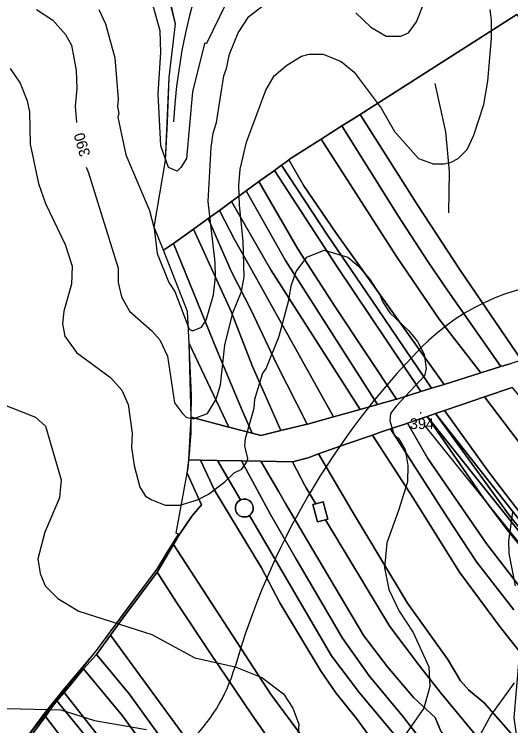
# Model space of a CAD drawing. Extents: x -510989 to -501240, y -1184665 to -1176098.
# Drawn here: x -505829.8 to -505553.2, y -1181865.9 to -1181469.7 of the extents above; entities that cross this region are included whole.
import ezdxf

# ---------------------------------------------------------------- set-up
doc = ezdxf.new("R2010")
doc.units = 0
for name, color, linetype in [('lesni_pozemek', 7, 'Continuous'), ('NAVRH_interakcni_prvky', 7, 'Continuous'), ('NAVRH_rozvodnice', 7, 'Continuous'), ('orna_puda', 7, 'Continuous'), ('ostatni_plocha_x_jina_plocha', 7, 'Continuous'), ('ostatni_plocha_x_ostatni_komunikace', 7, 'Continuous'), ('ostatni_plocha_x_silnice', 7, 'Continuous'), ('popis', 7, 'Continuous'), ('STAV_vyrazne_udolnice', 7, 'Continuous'), ('trasovani_toku', 7, 'Continuous'), ('trvaly_travni_porost', 7, 'Continuous'), ('vrstevnice_01', 7, 'Continuous'), ('vrstevnice_02', 7, 'Continuous'), ('vrstevnice_04', 7, 'Continuous'), ('vrstevnice_05', 7, 'Continuous')]:
    doc.layers.add(name, color=color, linetype=linetype)

msp = doc.modelspace()

# ---------------------------------------------------------------- linework, layer by layer
at = {"layer": 'lesni_pozemek'}
msp.add_lwpolyline([(-505549.95, -1181469.86), (-505637.13, -1181525.45), (-505642.17, -1181528.66), (-505647.29, -1181531.93), (-505658.89, -1181539.32), (-505676.4, -1181550.49), (-505676.84, -1181550.81), (-505678.71, -1181552.17), (-505680.89, -1181553.76), (-505684.89, -1181556.66), (-505693.47, -1181562.91), (-505700.54, -1181568.06), (-505708.78, -1181574.05), (-505715.54, -1181578.97), (-505721.81, -1181583.53), (-505729.98, -1181589.4), (-505740.99, -1181597.3), (-505744.98, -1181599.97), (-505746.66, -1181601.09), (-505751.84, -1181588.19), (-505745.47, -1181551.2), (-505744.49, -1181529.77), (-505743.54, -1181505.01), (-505739.97, -1181475.01), (-505742.3, -1181465.59)], dxfattribs=at)
at = {"layer": 'NAVRH_interakcni_prvky'}
msp.add_lwpolyline([(-505608.99, -1182282.38), (-505565.31, -1182197.02), (-505541.49, -1182095.78), (-505537.52, -1182014.39), (-505537.52, -1181958.81), (-505551.42, -1181861.54), (-505543.48, -1181770.22), (-505601.05, -1181698.76)], dxfattribs=at)
at = {"layer": 'NAVRH_rozvodnice'}
for centre, radius, start, end in [((-505515.12, -1181741.86), 123.42, 43.4368, 135.5965), ((-505303.11, -1181949.5), 420.17, 135.5965, 163.9032), ((-505797.18, -1181806.92), 94.05, 281.7653, 343.9032)]:
    msp.add_arc(centre, radius, start, end, dxfattribs=at)
at = {"layer": 'orna_puda'}
for points in [[(-505549.95, -1181469.86), (-505499.27, -1181550.32), (-505442.05, -1181628.22), (-505490.78, -1181643.73), (-505545.54, -1181661.83), (-505547.25, -1181662.36), (-505581.76, -1181611.58), (-505605.04, -1181576.13), (-505637.13, -1181525.45)], [(-505637.13, -1181525.45), (-505605.04, -1181576.13), (-505581.76, -1181611.58), (-505547.25, -1181662.36), (-505553.07, -1181664.17), (-505558.73, -1181665.93), (-505588.37, -1181623.74), (-505599.42, -1181607.32), (-505615.95, -1181582), (-505647.29, -1181531.93), (-505642.17, -1181528.66)], [(-505647.29, -1181531.93), (-505615.95, -1181582), (-505599.42, -1181607.32), (-505588.37, -1181623.74), (-505558.73, -1181665.93), (-505570, -1181669.44), (-505593.08, -1181639.52), (-505616.87, -1181604.64), (-505658.89, -1181539.32)], [(-505658.89, -1181539.32), (-505616.87, -1181604.64), (-505593.08, -1181639.52), (-505570, -1181669.44), (-505590.37, -1181675.78), (-505650.52, -1181591.58), (-505668.48, -1181565.17), (-505676.84, -1181550.81), (-505676.4, -1181550.49)], [(-505680.89, -1181553.76), (-505655.23, -1181592.68), (-505630.99, -1181628.34), (-505597.47, -1181677.99), (-505603.32, -1181679.81), (-505650.01, -1181610.34), (-505684.89, -1181556.66)], [(-505676.84, -1181550.81), (-505668.48, -1181565.17), (-505650.52, -1181591.58), (-505590.37, -1181675.78), (-505597.47, -1181677.99), (-505630.99, -1181628.34), (-505655.23, -1181592.68), (-505680.89, -1181553.76), (-505678.71, -1181552.17)], [(-505684.89, -1181556.66), (-505650.01, -1181610.34), (-505603.32, -1181679.81), (-505615.47, -1181683.59), (-505616.97, -1181684.01), (-505651, -1181632.53), (-505671.66, -1181600.64), (-505693.47, -1181562.91)], [(-505693.47, -1181562.91), (-505671.66, -1181600.64), (-505651, -1181632.53), (-505616.97, -1181684.01), (-505627.42, -1181686.96), (-505678.78, -1181606.77), (-505700.54, -1181568.06)], [(-505700.54, -1181568.06), (-505678.78, -1181606.77), (-505627.42, -1181686.96), (-505637.21, -1181689.71), (-505686.9, -1181612.05), (-505708.78, -1181574.05)], [(-505708.78, -1181574.05), (-505686.9, -1181612.05), (-505637.21, -1181689.71), (-505651.88, -1181693.84), (-505697.45, -1181612.17), (-505707.12, -1181595.2), (-505715.54, -1181578.97)], [(-505715.54, -1181578.97), (-505707.12, -1181595.2), (-505697.45, -1181612.17), (-505651.88, -1181693.84), (-505666.49, -1181697.96), (-505666.63, -1181697.99), (-505683.76, -1181664.34), (-505697.88, -1181634.52), (-505708.96, -1181612.84), (-505721.81, -1181583.53)], [(-505721.81, -1181583.53), (-505708.96, -1181612.84), (-505697.88, -1181634.52), (-505683.76, -1181664.34), (-505666.63, -1181697.99), (-505681.24, -1181701.51), (-505697.16, -1181665.75), (-505708.87, -1181635.15), (-505729.98, -1181589.4)], [(-505729.98, -1181589.4), (-505708.87, -1181635.15), (-505697.16, -1181665.75), (-505681.24, -1181701.51), (-505692.49, -1181704.21), (-505697.28, -1181702.95), (-505702.71, -1181690.7), (-505716.82, -1181657.04), (-505740.99, -1181597.3)], [(-505567.93, -1181682.77), (-505552.51, -1181677.59), (-505498.97, -1181743.64), (-505474.97, -1181771.05), (-505460.17, -1181785.84), (-505427.45, -1181814.53), (-505319.25, -1181908.55), (-505293.76, -1181934.91), (-505233.92, -1181995.14), (-505145.97, -1182076.96), (-505126.19, -1182097.18), (-505131.28, -1182105.44), (-505151.3, -1182085.2), (-505248.6, -1181994.46), (-505327.51, -1181915.16), (-505374.61, -1181873.77), (-505471.42, -1181794.36), (-505487.88, -1181779.75), (-505511, -1181753.67), (-505546.09, -1181711.4)], [(-505595.13, -1181692.03), (-505590.07, -1181690.28), (-505564.92, -1181725.42), (-505544.12, -1181752.43), (-505504.67, -1181800.24), (-505483.42, -1181824.61), (-505473.57, -1181836.02), (-505479.2, -1181830.55), (-505503.28, -1181808.61)], [(-505568.45, -1181739.06), (-505599.75, -1181693.62), (-505505.11, -1181812.14), (-505484.81, -1181831.31), (-505476.19, -1181841.29), (-505479.59, -1181848.15), (-505499.98, -1181824.6), (-505526.21, -1181792.13), (-505555.28, -1181756.75)], [(-505645.06, -1181709.14), (-505630.33, -1181704), (-505607.36, -1181739.3), (-505581.79, -1181780.35), (-505558.96, -1181811.1), (-505514.25, -1181867.52), (-505531.74, -1181873.34), (-505525.62, -1181879.39), (-505541.83, -1181883.21), (-505546.41, -1181877.85), (-505568.04, -1181853.19), (-505576.73, -1181845.92), (-505581.16, -1181840.91), (-505588.32, -1181829.06), (-505610.78, -1181797.53), (-505641.63, -1181746.38), (-505660.24, -1181714.54)], [(-505725.57, -1181742.85), (-505730.82, -1181749.23), (-505737.9, -1181759.57), (-505738.32, -1181759.25), (-505739.6, -1181758.57), (-505733.38, -1181725.22)]]:
    msp.add_lwpolyline(points, close=True, dxfattribs=at)
for points in [[(-505544.12, -1181752.43), (-505564.92, -1181725.42), (-505590.07, -1181690.28), (-505581.46, -1181687.31), (-505567.93, -1181682.77), (-505546.09, -1181711.4)], [(-505548.47, -1181788.37), (-505566.88, -1181764.28), (-505599.51, -1181717.13), (-505610.85, -1181697.45), (-505599.75, -1181693.62), (-505568.45, -1181739.06), (-505555.28, -1181756.75), (-505526.21, -1181792.13)], [(-505551.57, -1181801.41), (-505572.34, -1181774.68), (-505588.74, -1181749.81), (-505620.31, -1181700.6), (-505611.22, -1181697.58), (-505610.85, -1181697.45), (-505599.51, -1181717.13), (-505566.88, -1181764.28), (-505548.47, -1181788.37)], [(-505514.25, -1181867.52), (-505558.96, -1181811.1), (-505581.79, -1181780.35), (-505607.36, -1181739.3), (-505630.33, -1181704), (-505625.83, -1181702.44), (-505620.31, -1181700.6), (-505588.74, -1181749.81), (-505572.34, -1181774.68), (-505551.57, -1181801.41)], [(-505507.07, -1181935.7), (-505555.65, -1181891.64), (-505557.45, -1181889.34), (-505561.42, -1181884.84), (-505592.48, -1181847.24), (-505604.08, -1181832.44), (-505620.58, -1181810.68), (-505656.48, -1181751.17), (-505655.16, -1181750.82), (-505657.71, -1181741.15), (-505661.86, -1181742.24), (-505663.3, -1181739.86), (-505667.22, -1181733.35), (-505667.95, -1181732.15), (-505674.84, -1181718.93), (-505666.07, -1181716.62), (-505660.24, -1181714.54), (-505641.63, -1181746.38), (-505610.78, -1181797.53), (-505588.32, -1181829.06), (-505581.16, -1181840.91), (-505576.73, -1181845.92), (-505568.04, -1181853.19), (-505546.41, -1181877.85)], [(-505660.49, -1181883.83), (-505687.09, -1181848.17), (-505741.01, -1181764.89), (-505737.9, -1181759.57), (-505730.82, -1181749.23), (-505725.57, -1181742.85), (-505733.38, -1181725.22), (-505732.86, -1181722.42), (-505732.49, -1181717.83), (-505726.11, -1181717.95), (-505718.22, -1181734.78), (-505692.16, -1181777.99), (-505681.85, -1181797.48), (-505658.78, -1181835.7), (-505650.7, -1181847.6), (-505639.25, -1181861.87), (-505610.14, -1181901.47)], [(-505610.14, -1181901.47), (-505639.25, -1181861.87), (-505650.7, -1181847.6), (-505658.78, -1181835.7), (-505681.85, -1181797.48), (-505692.16, -1181777.99), (-505718.22, -1181734.78), (-505726.11, -1181717.95), (-505716.54, -1181718.14), (-505703.72, -1181740.12), (-505704.45, -1181740.55), (-505705.24, -1181741.21), (-505705.91, -1181742.06), (-505706.38, -1181743.05), (-505706.63, -1181744.13), (-505706.63, -1181745.22), (-505706.35, -1181746.41), (-505706.01, -1181747.15), (-505705.49, -1181747.92), (-505704.96, -1181748.44), (-505704.26, -1181748.96), (-505703.46, -1181749.31), (-505702.68, -1181749.58), (-505700.97, -1181749.63), (-505700.23, -1181749.48), (-505699.72, -1181749.27), (-505698.71, -1181748.71), (-505653.09, -1181826.96), (-505637.42, -1181847.45), (-505616.46, -1181872.67)], [(-505616.46, -1181872.67), (-505637.42, -1181847.45), (-505653.09, -1181826.96), (-505698.71, -1181748.71), (-505697.95, -1181748), (-505697.42, -1181747.29), (-505696.96, -1181746.42), (-505696.72, -1181745.41), (-505696.68, -1181744.32), (-505696.86, -1181743.28), (-505697.18, -1181742.5), (-505697.7, -1181741.69), (-505698.19, -1181741.05), (-505699.01, -1181740.46), (-505699.66, -1181740.12), (-505700.62, -1181739.79), (-505701.48, -1181739.7), (-505702.37, -1181739.71), (-505703.16, -1181739.89), (-505703.72, -1181740.12), (-505716.54, -1181718.14), (-505703.13, -1181718.39), (-505687.07, -1181748.28), (-505672.88, -1181772.78), (-505646.87, -1181817.03), (-505632.14, -1181838.14), (-505612.92, -1181861.05), (-505599.18, -1181878.9)], [(-505538.57, -1181942.08), (-505567.25, -1181916.64), (-505584.02, -1181898.83), (-505589.56, -1181892.12), (-505599.18, -1181878.9), (-505612.92, -1181861.05), (-505632.14, -1181838.14), (-505646.87, -1181817.03), (-505672.88, -1181772.78), (-505687.07, -1181748.28), (-505703.13, -1181718.39), (-505692.43, -1181718.6), (-505682.47, -1181735.61), (-505678.65, -1181742.13), (-505664.07, -1181767.03), (-505635.1, -1181815.8), (-505621.88, -1181833.09), (-505607.28, -1181850.35), (-505595.38, -1181861.22), (-505592.27, -1181868.87), (-505578.51, -1181887.2), (-505573.04, -1181894.67), (-505550.18, -1181917.35)], [(-505592.27, -1181868.87), (-505595.38, -1181861.22), (-505607.28, -1181850.35), (-505621.88, -1181833.09), (-505635.1, -1181815.8), (-505664.07, -1181767.03), (-505678.65, -1181742.13), (-505682.47, -1181735.61), (-505692.43, -1181718.6), (-505674.84, -1181718.93), (-505667.95, -1181732.15), (-505667.22, -1181733.35), (-505663.3, -1181739.86), (-505661.86, -1181742.24), (-505663.51, -1181742.67), (-505660.96, -1181752.35), (-505656.48, -1181751.17), (-505620.58, -1181810.68), (-505604.08, -1181832.44), (-505592.48, -1181847.24), (-505561.42, -1181884.84)], [(-505825.06, -1181875.34), (-505813.07, -1181859.24), (-505802.44, -1181846.06), (-505795.38, -1181837.73), (-505784.46, -1181824.63), (-505764.61, -1181797.74), (-505750.28, -1181778.84), (-505743.77, -1181768.19), (-505738.32, -1181759.25), (-505737.9, -1181759.57), (-505741.01, -1181764.89), (-505750.08, -1181780.4), (-505769.3, -1181805.97), (-505776.1, -1181815.46), (-505783.89, -1181826.23), (-505791.17, -1181834.24), (-505798.23, -1181842.98), (-505801.99, -1181847.3), (-505805.97, -1181852.06), (-505808.59, -1181855.27), (-505812.34, -1181860.62), (-505820.57, -1181871.69)], [(-505449.63, -1182114.77), (-505566.1, -1182010.76), (-505636.02, -1181946.35), (-505666.73, -1181903.35), (-505697.28, -1181859.94), (-505720.51, -1181825.65), (-505739.62, -1181796.79), (-505750.08, -1181780.4), (-505741.01, -1181764.89), (-505687.09, -1181848.17), (-505660.49, -1181883.83), (-505634.94, -1181918.67), (-505631.57, -1181922.99), (-505623.96, -1181932.93), (-505584.61, -1181971.35), (-505549.33, -1182005.12)], [(-505548.69, -1182072.33), (-505575.74, -1182046.26), (-505607.3, -1182021.49), (-505628.49, -1182002.74), (-505642.51, -1181989.57), (-505666.31, -1181964.35), (-505679.02, -1181948.82), (-505715.14, -1181898.95), (-505776.1, -1181815.46), (-505769.3, -1181805.97), (-505750.08, -1181780.4), (-505739.62, -1181796.79), (-505720.51, -1181825.65), (-505697.28, -1181859.94), (-505666.73, -1181903.35), (-505636.02, -1181946.35), (-505566.1, -1182010.76), (-505449.63, -1182114.77)], [(-505546.57, -1182087.4), (-505591.18, -1182045.46), (-505630.08, -1182015.76), (-505651.04, -1181995.93), (-505671.69, -1181975.7), (-505675.24, -1181971.59), (-505702.79, -1181935.13), (-505765.81, -1181848.01), (-505783.89, -1181826.23), (-505776.1, -1181815.46), (-505715.14, -1181898.95), (-505679.02, -1181948.82), (-505666.31, -1181964.35), (-505642.51, -1181989.57), (-505628.49, -1182002.74), (-505607.3, -1182021.49), (-505575.74, -1182046.26), (-505548.69, -1182072.33)], [(-505529.84, -1182114.76), (-505588.6, -1182063.62), (-505636.85, -1182023.91), (-505662.46, -1182001.15), (-505683, -1181978.33), (-505695.81, -1181963.06), (-505734.2, -1181911.27), (-505751.18, -1181885.54), (-505769.45, -1181860.32), (-505791.17, -1181834.24), (-505783.89, -1181826.23), (-505765.81, -1181848.01), (-505702.79, -1181935.13), (-505675.24, -1181971.59), (-505671.69, -1181975.7), (-505651.04, -1181995.93), (-505630.08, -1182015.76), (-505591.18, -1182045.46), (-505546.57, -1182087.4)], [(-505528.18, -1182137.53), (-505577.6, -1182094), (-505625.15, -1182052.03), (-505645.72, -1182036.13), (-505670.84, -1182012.86), (-505693.22, -1181990.05), (-505713.98, -1181965.62), (-505749.67, -1181918.15), (-505760.65, -1181899.98), (-505801.99, -1181847.3), (-505798.23, -1181842.98), (-505791.17, -1181834.24), (-505769.45, -1181860.32), (-505751.18, -1181885.54), (-505734.2, -1181911.27), (-505695.81, -1181963.06), (-505683, -1181978.33), (-505662.46, -1182001.15), (-505636.85, -1182023.91), (-505588.6, -1182063.62), (-505529.84, -1182114.76)], [(-505532.27, -1182141.24), (-505587.42, -1182091.43), (-505614.77, -1182067.94), (-505643.09, -1182044.56), (-505661.6, -1182028.61), (-505695.87, -1181995.88), (-505717.21, -1181970.31), (-505736.62, -1181944.38), (-505759.68, -1181911.96), (-505781.9, -1181881.56), (-505805.97, -1181852.06), (-505801.99, -1181847.3), (-505760.65, -1181899.98), (-505749.67, -1181918.15), (-505713.98, -1181965.62), (-505693.22, -1181990.05), (-505670.84, -1182012.86), (-505645.72, -1182036.13), (-505625.15, -1182052.03), (-505577.6, -1182094), (-505528.18, -1182137.53)], [(-505532.37, -1182154.29), (-505570.03, -1182119.63), (-505607, -1182087.75), (-505616.44, -1182079.3), (-505647.43, -1182055.24), (-505680.27, -1182024.87), (-505704.76, -1182001.46), (-505715.8, -1181988.14), (-505746.51, -1181948.8), (-505771.43, -1181914.01), (-505812.34, -1181860.62), (-505808.59, -1181855.27), (-505805.97, -1181852.06), (-505781.9, -1181881.56), (-505759.68, -1181911.96), (-505736.62, -1181944.38), (-505717.21, -1181970.31), (-505695.87, -1181995.88), (-505661.6, -1182028.61), (-505643.09, -1182044.56), (-505614.77, -1182067.94), (-505587.42, -1182091.43), (-505532.27, -1182141.24)], [(-505536.68, -1182165.35), (-505591.42, -1182115.18), (-505675.93, -1182043.56), (-505709.79, -1182011.3), (-505729.39, -1181989.04), (-505761.15, -1181948.45), (-505776.69, -1181924.96), (-505820.57, -1181871.69), (-505812.34, -1181860.62), (-505771.43, -1181914.01), (-505746.51, -1181948.8), (-505715.8, -1181988.14), (-505704.76, -1182001.46), (-505680.27, -1182024.87), (-505647.43, -1182055.24), (-505616.44, -1182079.3), (-505607, -1182087.75), (-505570.03, -1182119.63), (-505532.37, -1182154.29)]]:
    msp.add_lwpolyline(points, dxfattribs=at)
at = {"layer": 'ostatni_plocha_x_jina_plocha'}
for points in [[(-505702.37, -1181739.71), (-505701.48, -1181739.7), (-505700.62, -1181739.79), (-505699.66, -1181740.12), (-505699.01, -1181740.46), (-505698.19, -1181741.05), (-505697.7, -1181741.69), (-505697.18, -1181742.5), (-505696.86, -1181743.28), (-505696.68, -1181744.32), (-505696.72, -1181745.41), (-505696.96, -1181746.42), (-505697.42, -1181747.29), (-505697.95, -1181748), (-505698.71, -1181748.71), (-505699.72, -1181749.27), (-505700.23, -1181749.48), (-505700.97, -1181749.63), (-505702.68, -1181749.58), (-505703.46, -1181749.31), (-505704.26, -1181748.96), (-505704.96, -1181748.44), (-505705.49, -1181747.92), (-505706.01, -1181747.15), (-505706.35, -1181746.41), (-505706.63, -1181745.22), (-505706.63, -1181744.13), (-505706.38, -1181743.05), (-505705.91, -1181742.06), (-505705.24, -1181741.21), (-505704.45, -1181740.55), (-505703.72, -1181740.12), (-505703.16, -1181739.89)], [(-505661.86, -1181742.24), (-505657.71, -1181741.15), (-505655.16, -1181750.82), (-505656.48, -1181751.17), (-505660.96, -1181752.35), (-505663.51, -1181742.67)]]:
    msp.add_lwpolyline(points, close=True, dxfattribs=at)
at = {"layer": 'ostatni_plocha_x_ostatni_komunikace'}
for points in [[(-505599.75, -1181693.62), (-505595.13, -1181692.03), (-505554.15, -1181748.53), (-505518.11, -1181792.77), (-505505.49, -1181807.38), (-505484.81, -1181831.31), (-505505.11, -1181812.14)], [(-505554.15, -1181748.53), (-505595.13, -1181692.03), (-505503.28, -1181808.61), (-505479.2, -1181830.55), (-505473.57, -1181836.02), (-505475.57, -1181840.04), (-505484.81, -1181831.31), (-505505.49, -1181807.38), (-505518.11, -1181792.77)]]:
    msp.add_lwpolyline(points, close=True, dxfattribs=at)
at = {"layer": 'ostatni_plocha_x_silnice'}
msp.add_lwpolyline([(-505552.51, -1181677.59), (-505567.93, -1181682.77), (-505581.46, -1181687.31), (-505590.07, -1181690.28), (-505595.13, -1181692.03), (-505599.75, -1181693.62), (-505610.85, -1181697.45), (-505611.22, -1181697.58), (-505620.31, -1181700.6), (-505625.83, -1181702.44), (-505630.33, -1181704), (-505645.06, -1181709.14), (-505660.24, -1181714.54), (-505666.07, -1181716.62), (-505674.84, -1181718.93), (-505692.43, -1181718.6), (-505703.13, -1181718.39), (-505716.54, -1181718.14), (-505726.11, -1181717.95), (-505732.49, -1181717.83), (-505732.21, -1181714.38), (-505731.62, -1181707.13), (-505731.31, -1181703.33), (-505731.24, -1181694.06), (-505710.23, -1181699.56), (-505701.54, -1181701.84), (-505697.28, -1181702.95), (-505692.49, -1181704.21), (-505681.24, -1181701.51), (-505666.63, -1181697.99), (-505666.49, -1181697.96), (-505651.88, -1181693.84), (-505637.21, -1181689.71), (-505627.42, -1181686.96), (-505616.97, -1181684.01), (-505615.47, -1181683.59), (-505603.32, -1181679.81), (-505597.47, -1181677.99), (-505590.37, -1181675.78), (-505570, -1181669.44), (-505558.73, -1181665.93), (-505553.07, -1181664.17)], dxfattribs=at)
at = {"layer": 'popis'}
msp.add_lwpolyline([(-505825.06, -1181875.34), (-505784.46, -1181824.63), (-505750.28, -1181778.84), (-505738.32, -1181759.25), (-505739.6, -1181758.57), (-505733.38, -1181725.22), (-505732.49, -1181717.83), (-505731.24, -1181694.06), (-505732.44, -1181653.08), (-505733.24, -1181635.17), (-505746.66, -1181601.09), (-505751.84, -1181588.19), (-505745.47, -1181551.2), (-505743.54, -1181505.01), (-505739.97, -1181475.01), (-505744.32, -1181455.85)], dxfattribs=at)
at = {"layer": 'STAV_vyrazne_udolnice'}
msp.add_lwpolyline([(-505595.6, -1181508.3), (-505589.57, -1181535.22), (-505587.56, -1181557.32), (-505587.96, -1181580.21)], dxfattribs=at)
at = {"layer": 'trasovani_toku'}
for p, q in [((-505729.63, -1181460.71), (-505732.14, -1181470.39)), ((-505732.14, -1181470.39), (-505734.38, -1181480.13)), ((-505734.38, -1181480.13), (-505736.46, -1181489.91)), ((-505736.46, -1181489.91), (-505737.95, -1181499.8)), ((-505737.95, -1181499.8), (-505739.45, -1181509.69)), ((-505739.45, -1181509.69), (-505740.27, -1181519.65)), ((-505740.27, -1181519.65), (-505741.1, -1181529.62))]:
    msp.add_line(p, q, dxfattribs=at)
at = {"layer": 'trvaly_travni_porost'}
for points in [[(-505740.99, -1181597.3), (-505716.82, -1181657.04), (-505702.71, -1181690.7), (-505697.28, -1181702.95), (-505701.54, -1181701.84), (-505710.23, -1181699.56), (-505732.44, -1181653.08), (-505733.24, -1181635.17), (-505746.66, -1181601.09), (-505744.98, -1181599.97)], [(-505731.14, -1181682.01), (-505732.44, -1181653.08), (-505710.23, -1181699.56), (-505731.24, -1181694.06)]]:
    msp.add_lwpolyline(points, close=True, dxfattribs=at)
at = {"layer": 'vrstevnice_01'}
for points in [[(-505712, -1181464), (-505722.69, -1181486), (-505723.81, -1181486), (-505730.41, -1181513), (-505733.81, -1181550), (-505736.91, -1181555), (-505739.09, -1181557), (-505743.91, -1181555), (-505748.19, -1181543), (-505749.59, -1181514), (-505748.09, -1181491), (-505748.5, -1181479), (-505752.41, -1181465)], [(-505817.41, -1181467), (-505808.31, -1181473), (-505801.31, -1181481), (-505797.91, -1181487), (-505795.19, -1181501), (-505795, -1181511), (-505795.91, -1181521), (-505795.07, -1181529.91)], [(-505789.71, -1181554.87), (-505788.41, -1181558), (-505771.81, -1181611), (-505771.81, -1181619), (-505770, -1181627), (-505765.59, -1181635), (-505753.19, -1181646), (-505748.69, -1181651), (-505744.41, -1181660), (-505740.5, -1181686), (-505736, -1181692), (-505734.09, -1181694), (-505730.09, -1181695), (-505722.19, -1181692), (-505717.31, -1181684), (-505714.81, -1181676), (-505712.41, -1181654), (-505708, -1181636), (-505703.19, -1181624), (-505701.81, -1181616), (-505702.31, -1181596), (-505704.41, -1181576), (-505704.69, -1181565), (-505703.91, -1181556), (-505700.5, -1181541), (-505689.59, -1181512), (-505685, -1181504), (-505678, -1181498), (-505669.81, -1181493), (-505665.59, -1181492), (-505657.69, -1181492), (-505647.69, -1181496), (-505640.41, -1181502), (-505625.5, -1181522), (-505617.91, -1181535), (-505604.69, -1181550), (-505596.41, -1181553), (-505590.41, -1181553), (-505586.5, -1181552), (-505582.5, -1181550), (-505577.59, -1181545), (-505573.81, -1181537), (-505568.31, -1181520), (-505566.09, -1181507), (-505564, -1181483), (-505563.91, -1181473), (-505564.69, -1181467)], [(-505838.31, -1181686), (-505818, -1181694), (-505812.31, -1181699), (-505803.69, -1181729), (-505804.5, -1181739), (-505812.81, -1181758), (-505816.59, -1181773), (-505815.31, -1181781), (-505812.59, -1181788), (-505805.5, -1181795), (-505793.81, -1181802), (-505753.19, -1181815), (-505729.19, -1181828), (-505706.81, -1181833), (-505691.81, -1181839), (-505679.81, -1181848), (-505674.69, -1181856), (-505671.19, -1181865), (-505672.41, -1181880)], [(-505552.31, -1181747), (-505554.5, -1181763), (-505554.31, -1181770), (-505550.81, -1181788)], [(-505551.41, -1181842), (-505564.41, -1181860), (-505572.5, -1181875), (-505572.81, -1181884), (-505571.09, -1181889), (-505564.69, -1181897), (-505556, -1181902), (-505542.81, -1181909)]]:
    msp.add_lwpolyline(points, dxfattribs=at)
at = {"layer": 'vrstevnice_02'}
for points in [[(-505782.59, -1181467), (-505779, -1181475), (-505773.81, -1181494), (-505771.91, -1181517), (-505772.31, -1181521), (-505771.59, -1181525), (-505772, -1181527), (-505767.69, -1181548), (-505754.41, -1181579), (-505751.81, -1181589), (-505750.09, -1181603), (-505743.59, -1181619), (-505740.31, -1181624), (-505732.41, -1181645), (-505730.5, -1181646), (-505725.5, -1181644), (-505722.81, -1181640), (-505718.81, -1181626), (-505717.69, -1181616), (-505717.81, -1181608), (-505721.81, -1181574), (-505720.09, -1181544), (-505718.91, -1181536), (-505717.19, -1181530), (-505713.09, -1181504), (-505711.5, -1181500), (-505709.81, -1181492), (-505705, -1181480), (-505699.09, -1181471), (-505688.81, -1181463)], [(-505639.5, -1181469), (-505631.09, -1181477), (-505622.59, -1181482), (-505618.59, -1181482), (-505614.5, -1181482), (-505610.19, -1181480), (-505605.69, -1181474), (-505602.31, -1181465)], [(-505832, -1181500), (-505826.5, -1181508), (-505822.5, -1181518), (-505821.31, -1181524), (-505820.81, -1181542), (-505816.31, -1181564), (-505812.31, -1181575), (-505801.5, -1181598), (-505797.5, -1181610), (-505797.81, -1181620), (-505802.19, -1181635), (-505802.81, -1181642), (-505801.59, -1181649), (-505795.09, -1181658), (-505776.09, -1181672), (-505769.91, -1181679), (-505766.31, -1181687), (-505764.09, -1181703), (-505764.5, -1181711), (-505762.91, -1181721), (-505759.81, -1181733), (-505756.69, -1181738), (-505753.19, -1181740), (-505745.81, -1181743), (-505737.59, -1181743), (-505727.69, -1181740), (-505721.5, -1181737), (-505712.41, -1181730), (-505707.31, -1181725), (-505703.09, -1181723), (-505700.19, -1181719), (-505699.59, -1181717), (-505701.31, -1181710), (-505700.91, -1181706), (-505696.09, -1181689), (-505695.69, -1181684), (-505691.59, -1181670), (-505689.41, -1181667), (-505682.31, -1181649), (-505676.91, -1181629), (-505675.5, -1181621), (-505672.81, -1181613), (-505666.91, -1181605), (-505657.19, -1181601), (-505643.91, -1181605), (-505638, -1181610), (-505632, -1181617), (-505626.19, -1181626), (-505624.5, -1181630), (-505620.59, -1181636), (-505610.09, -1181646), (-505605.19, -1181652), (-505601.41, -1181659), (-505600.31, -1181667), (-505601.31, -1181671), (-505617, -1181688), (-505620.19, -1181692), (-505620.59, -1181696), (-505618.19, -1181704), (-505615.5, -1181706), (-505612.09, -1181712), (-505610.5, -1181721), (-505610.81, -1181730), (-505615.69, -1181746), (-505622.31, -1181764), (-505623.59, -1181778), (-505621.19, -1181790), (-505615.41, -1181802), (-505607.59, -1181814), (-505598.81, -1181833), (-505598.31, -1181844), (-505601.59, -1181856), (-505612, -1181871)], [(-505841.59, -1181856), (-505803.81, -1181857), (-505785, -1181863), (-505756.19, -1181868)]]:
    msp.add_lwpolyline(points, dxfattribs=at)

# ---------------------------------------------------------------- texts
at = {"layer": 'vrstevnice_04'}
msp.add_text('390', height=6, rotation=106.186, dxfattribs=at).set_placement((-505787.28, -1181547.98))
at = {"layer": 'vrstevnice_05'}
for s, p in [('.', (-505604.58, -1181692.07)), ('394', (-505609.43, -1181700.67))]:
    msp.add_text(s, height=6, dxfattribs=at).set_placement(p)

doc.saveas('drawing.dxf')
